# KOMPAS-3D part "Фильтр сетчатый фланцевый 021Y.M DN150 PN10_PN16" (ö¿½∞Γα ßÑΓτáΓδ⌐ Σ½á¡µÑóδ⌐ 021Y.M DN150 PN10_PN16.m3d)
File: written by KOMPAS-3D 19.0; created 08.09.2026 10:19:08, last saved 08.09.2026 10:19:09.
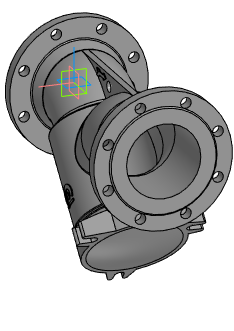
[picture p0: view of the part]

Document properties: Автор: user; Полное имя файла: Z:\3.Личные\sachek\Dendor\_3D для проектировщиков\8.2 Фильтр сетчатый 021Y.M\021Y.M_STP\Фильтр сетчатый фланцевый 021Y.M DN150 PN10_PN16.m3d

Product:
- Part/product: Фильтр сетчатый фланцевый 021Y.M DN150 PN10_PN16
    Масса: 52.3892

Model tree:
1. Операция без истории:1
